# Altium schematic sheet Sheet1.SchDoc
size A3; DrawnBy: Babakyan Ruslan
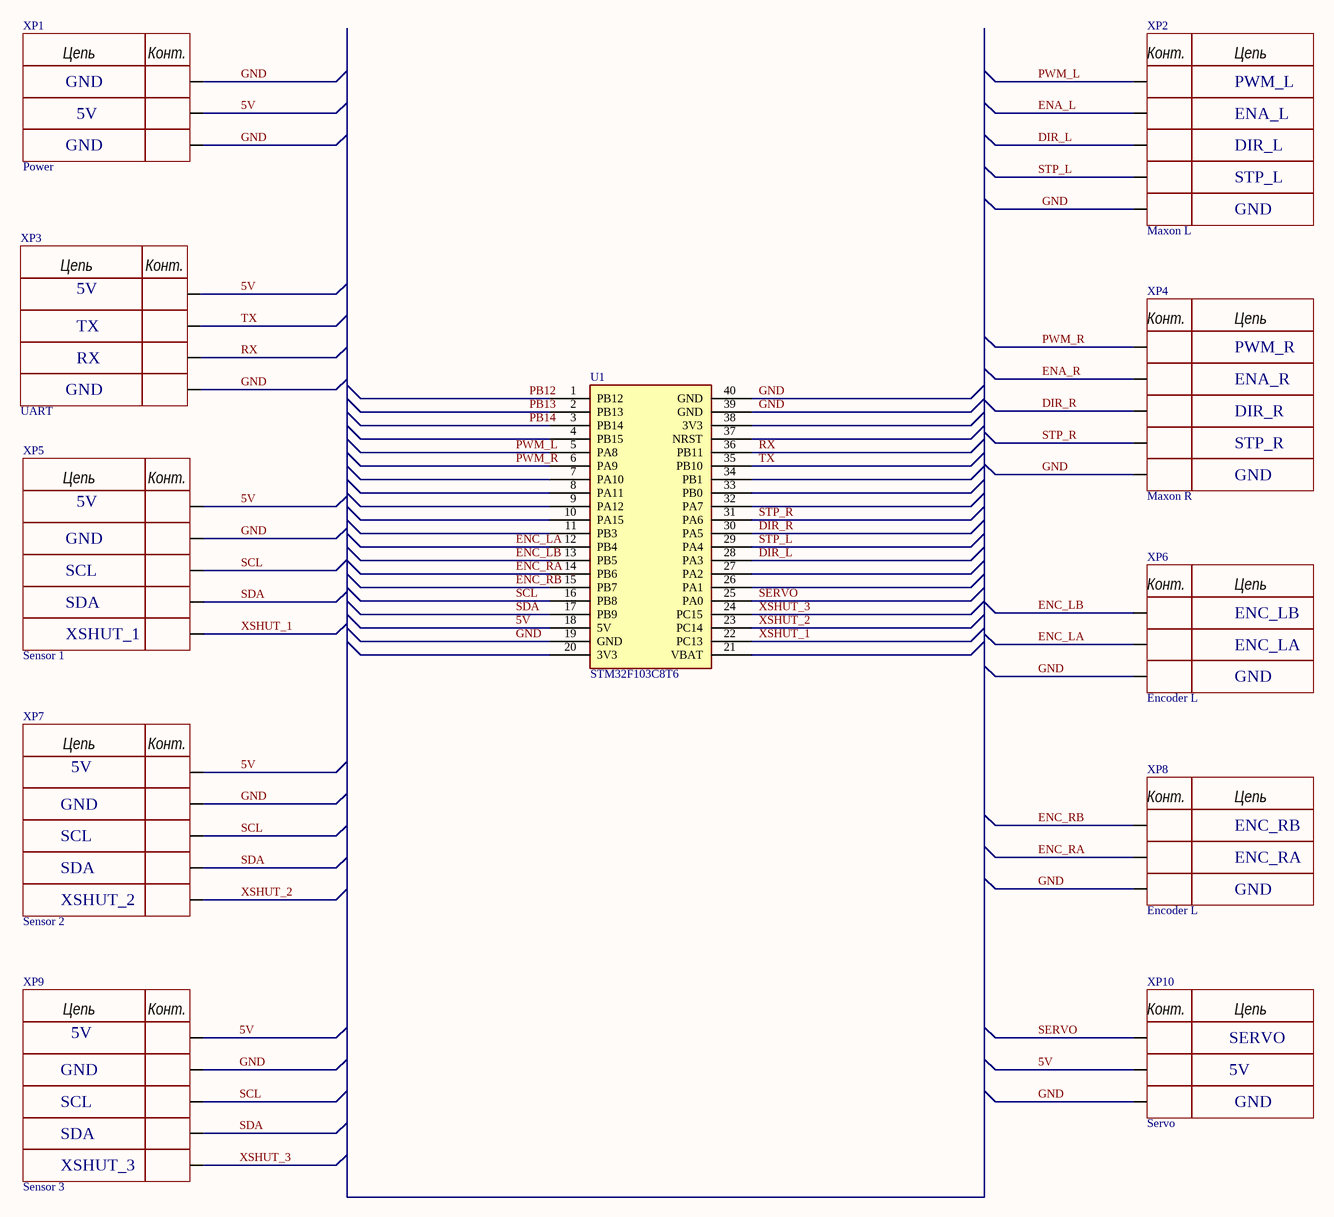
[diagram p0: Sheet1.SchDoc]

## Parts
U1  STM32F103C8T6  [Stm32 BluePill]
XP1  Power  [B3B-PH-K-S]
XP2  Maxon L  [B5B-PH-K-S]
XP3  UART  [B4B-PH-K-S]
XP4  Maxon R  [B5B-PH-K-S]
XP5  Sensor 1  [B5B-PH-K-S]
XP6  Encoder L  [B3B-PH-K-S]
XP7  Sensor 2  [B5B-PH-K-S]
XP8  Encoder L  [B3B-PH-K-S]
XP9  Sensor 3  [B5B-PH-K-S]
XP10  Servo  [B3B-PH-K-S]

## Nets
5V: U1.18(5V) XP1.2 XP3.1 XP5.1 XP7.1 XP9.1 XP10.2
DIR_L: U1.28(PA3) XP2.3
DIR_R: U1.30(PA5) XP4.3
ENA_L: XP2.2
ENA_R: XP4.2
ENC_LA: U1.12(PB4) XP6.2
ENC_LB: U1.13(PB5) XP6.1
ENC_RA: U1.14(PB6) XP8.2
ENC_RB: U1.15(PB7) XP8.1
GND: U1.19(GND) U1.39(GND) U1.40(GND) XP1.1 XP1.3 XP2.5 XP3.4 XP4.5 XP5.2 XP6.3 XP7.2 XP8.3 XP9.2 XP10.3
PB12: U1.1(PB12)
PB13: U1.2(PB13)
PB14: U1.3(PB14)
PWM_L: U1.5(PA8) XP2.1
PWM_R: U1.6(PA9) XP4.1
RX: U1.36(PB11) XP3.3
SCL: U1.16(PB8) XP5.3 XP7.3 XP9.3
SDA: U1.17(PB9) XP5.4 XP7.4 XP9.4
SERVO: U1.25(PA0) XP10.1
STP_L: U1.29(PA4) XP2.4
STP_R: U1.31(PA6) XP4.4
TX: U1.35(PB10) XP3.2
XSHUT_1: U1.22(PC13) XP5.5
XSHUT_2: U1.23(PC14) XP7.5
XSHUT_3: U1.24(PC15) XP9.5

Not connected (* = marked no-connect by the designer): U1 4(PB15) 7(PA10) 8(PA11) 9(PA12) 10(PA15) 11(PB3) 20(3V3) 21(VBAT) 26(PA1) 27(PA2) 32(PA7) 33(PB0) 34(PB1) 37(NRST) 38(3V3)

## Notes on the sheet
- GND
- PWM_L
- 5V
- DIR_L
- ENA_L
- STP_L
- TX
- RX
- PWM_R
- DIR_R
- ENA_R
- STP_R
- SCL
- SDA
- XSHUT_1
- ENC_LB
- ENC_LA
- ENC_RB
- XSHUT_2
- ENC_RA
- SERVO
- XSHUT_3

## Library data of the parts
U1 = BluePill: Designed By @Alixahedi
XP1 XP6 XP8 XP10 = B3B-PH-K-S: Manufacturer: JST Corporation; Name: B4B-PH-K-S; PHR-4; SPH-002T-P0.5*; Group: Соединение контактное типа штырь
XP2 XP4 XP5 XP7 XP9 = B5B-PH-K-S
XP3 = B4B-PH-K-S: Manufacturer: JST Corporation; Name: B4B-PH-K-S; PHR-4; SPH-002T-P0.5*; Group: Соединение контактное типа штырь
